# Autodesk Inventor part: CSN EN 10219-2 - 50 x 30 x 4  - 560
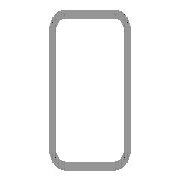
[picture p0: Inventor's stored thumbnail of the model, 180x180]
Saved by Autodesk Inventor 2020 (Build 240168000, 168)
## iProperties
Created: 2019-01
Part Number: CSN EN 10219-2 - 50 x 30 x 4  - 560
Material: Ocel, měkká
Description: Duté svařované profily tvářené za studena z nelegované a jemnozrnné konstrukční oceli
Document SubType Name: Modeling
Standard: CSN EN 10219-2
Designer: doma
Standards Organization: CSN
Language: cs-CZ
Size Designation: 50 x 30 x 4  - 560
Categories: <MemberInstance><Categories><Category DisplayName="Konstrukční profily" InternalName="089c4875-fa83-4c05-b084-43b9cc11f5ed" Mnemonic="GRDR"><CategoryParameter D
Stock Number: 50 x 30 x 4
Density: 7.85 g/cm^3
Appearance: Pololeštěná
Mass: 2320.14 g
Surface Area: 1494.77 cm^2
Volume: 295.559 cm^3
IsCustomPart: 1
G_L: 560,000 mm
Author: doma
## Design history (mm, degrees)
node "Počáteční rovina"
node "Koncová rovina"
sketch "Náčrt"
  geometry: L1 (-15, -17)-(-15, 17); L2 (-7, 25)-(7, 25); L3 (15, 17)-(15, -17); L4 (7, -25)-(-7, -25); L5 (-7, 21)-(7, 21); L6 (11, 17)-(11, -17); L7 (7, -21)-(-7, -21); L8 (-11, -17)-(-11, 17); L9 (0, 37.32)-(0, -37.32) reference; L10 (-23.32, 0)-(23.32, 0) reference; A1 r 8 centre (-7, -17) between (-15, -17) and (-7, -25); A2 r 8 centre (-7, 17) between (-7, 25) and (-15, 17); A3 r 8 centre (7, 17) between (15, 17) and (7, 25); A4 r 8 centre (7, -17) between (7, -25) and (15, -17); A5 r 4 centre (-7, 17) between (-7, 21) and (-11, 17); A6 r 4 centre (7, 17) between (11, 17) and (7, 21); A7 r 4 centre (7, -17) between (7, -21) and (11, -17); A8 r 4 centre (-7, -17) between (-11, -17) and (-7, -21)
  constraints: 16 end point, 16 point on circle, 8 centre point, 8 tangent, 4 parallel, 3 equal radius, 2 perpendicular, 7 other
  dimensions: "d7" = 8 radius of A1 (= G_IR); "d10" = 50 distance between parallel lines of L2 L4 (= G_H); "d11" = 30 distance between parallel lines of L1 L3 (= G_W); "d12" = 4 distance between parallel lines of L3 L6 (= G_T); "d15" = 25 distance between parallel lines of L2 L10 (= 0.5 x d10); "d16" = 15 distance between parallel lines of L9 L3 (= 0.5 x d11)
extrude "Těleso" new body sketch "Náčrt" stored distance "d3" = 520; taper "d4" = 0 deg
node "Driven Length"
  sketch "Sketch3"
    geometry: L1 (0, 0)-(10, 0) reference
    constraints: 2 end point, 1 horizontal
  workplane "Work Plane3"
  sketch "Sketch4"
    geometry: L1 (-2, 0)-(12, 0) reference; L2 (-2, 560)-(12, 560) reference
    dimensions: "d18" = 560 distance between parallel lines of L1 L2 (derived)
sketch "Náčrt5"
  geometry: L1 (560, 17)-(-155, 17); L2 (40, 34)-(40, 0) reference; 1 further point
  constraints: 2 end point, 1 midpoint
  dimensions: "d27" = 162.5 distance from line of L2 point (202.5, 17)
hole "Díra1" sketch "Náčrt5" diameter "d19" = 13; stored, may be unused: countersink angle "d23" = 90 deg, drill point angle "d25" = 118 deg; dims "d20" = 6, "d21" = 4, "d22" = 2, "d24" = 8
body "Solid1"
other parameters: "G_W" = 30 [user parameter; used in 1 equation term], "G_H" = 50 [user parameter; used in 1 equation term], "G_T" = 4 [user parameter; used in 1 equation term], "G_IR" = 8 [user parameter; used in 1 equation term], "G_L" = 560 (= d18) [user parameter], "G_OFFSET_START" = 0 [user parameter; used in 1 equation term], "G_OFFSET_END" = 0 [user parameter; used in 1 equation term], "d13" = 0 (computed from G_OFFSET_START), "d17" = 90 deg
